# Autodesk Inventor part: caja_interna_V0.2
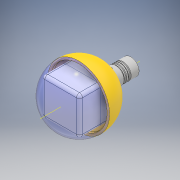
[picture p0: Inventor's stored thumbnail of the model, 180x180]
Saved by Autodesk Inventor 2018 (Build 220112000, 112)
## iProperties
Created: 2018-09
Part Number: caja_interna_V0.2
Material: Generic
Document SubType Name: Modeling
Designer: Gordillo
Density: 1 g/cm^3
Appearance: Default
Author: Gordillo
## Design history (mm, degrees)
sketch "Sketch1"
  geometry: L1 (125, 125)-(-125, 125); L2 (-125, 125)-(-125, -125); L3 (-125, -125)-(125, -125); L4 (125, -125)-(125, 125); L5 (-175, 0)-(175, 0) reference; L6 (0, -175)-(0, 175) reference; 1 further point
  constraints: 8 end point, 2 parallel, 1 horizontal, 1 perpendicular, 2 other
  dimensions: "d0" = 250 distance of L3.end L2.end; "d1" = 250 distance of L2.end L1.end
extrude "Extrusion1" new body sketch "Sketch1" distance "d2" = 220; taper "d3" = 0 deg
fillet "Fillet1" dims "d5" = 20
sketch "Sketch2"
  geometry: L1 (20, 125)-(220, 125) reference; L2 (120, 125)-(120, -125); L3 (220, -125)-(20, -125) reference; L4 (120, 125)-(120, 205); L5 (120, 0)-(-80, 0); L6 (-153.152, 0)-(282.192, 0) reference; A1 r 203.001 centre (122.991, 2.021) between (120, 205) and (-80, 0); 1 further point
  constraints: 6 end point, 3 midpoint, 2 point on circle, 1 centre point, 1 horizontal, 1 vertical
  dimensions: "d6" = 200 distance of L5.start L5.end; "d8" = 80 distance of L2.start L4.end
revolve "Revolution1" sketch "Sketch2" stored, may be unused: angle "d9" = 90 deg
combine "Combine1"
shell "Shell2" dims "d10" = 25
sketch "Sketch3"
  geometry: L1 (100, 100)-(100, -100) reference; L2 (100, -100)-(-100, -100) reference; L3 (-100, -100)-(-100, 100) reference; L4 (-100, 100)-(100, 100) reference; L5 (105, 125)-(-105, 125) reference; L6 (-125, 105)-(-125, -105) reference; L7 (-105, -125)-(105, -125) reference; L8 (125, -105)-(125, 105) reference; L9 (-105, 125)-(105, 125) reference; L10 (125, 105)-(125, -105) reference; L11 (105, -125)-(-105, -125) reference; L12 (-125, -105)-(-125, 105) reference; L13 (-105, 125)-(105, 125) reference; L14 (105, 125)-(-105, 125); L15 (-105, 125)-(-125, 105); L16 (-125, -105)-(-125, 105) reference; L17 (-125, -105)-(-105, -125); L18 (125, 105)-(125, -105) reference; L19 (105, -125)-(125, -105); L20 (125, -105)-(125, 105); L21 (-125, 105)-(-105, 105) reference; L22 (-125, 105)-(-125, -105); L23 (-105, -125)-(105, -125); C1 r 205 at (0, 0) reference; C2 r 189 at (0, 0); C3 r 205 at (0, 0) reference; A1 r 20 centre (105, 105) between (125, 105) and (105, 125) reference; A2 r 20 centre (-105, 105) between (-105, 125) and (-125, 105) reference; A3 r 20 centre (-105, -105) between (-125, -105) and (-105, -125) reference; A4 r 20 centre (105, -105) between (105, -125) and (125, -105) reference; A5 r 20 centre (-105, 105) between (-105, 125) and (-125, 105) reference; A6 r 20 centre (105, 105) between (125, 105) and (105, 125) reference; A7 r 20 centre (105, -105) between (105, -125) and (125, -105) reference; A8 r 20 centre (-105, -105) between (-125, -105) and (-105, -125) reference; A9 r 20 centre (105, 105) between (125, 105) and (105, 125) reference; A10 r 20 centre (105, 105) between (125, 105) and (105, 125); A11 r 20 centre (105, -105) between (105, -125) and (125, -105) reference; A12 r 20 centre (105, -105) between (105, -125) and (125, -105); A13 r 20 centre (-105, -105) between (-125, -105) and (-105, -125); A14 r 20 centre (-105, 105) between (-105, 125) and (-125, 105) reference; A15 r 20 centre (-105, 105) between (-105, 125) and (-125, 105); A16 r 20 centre (-105, -105) between (-125, -105) and (-105, -125); A17 r 20 centre (-105, -105) between (-125, -105) and (-105, -125); A18 r 20 centre (105, -105) between (105, -125) and (125, -105); A19 r 20 centre (-105, -105) between (-125, -105) and (-105, -125) reference; A20 r 20 centre (-105, -105) between (-125, -105) and (-105, -125); 1 further point
  constraints: 16 point on circle, 14 end point, 9 centre point, 3 perpendicular, 3 tangent, 2 collinear, 1 concentric, 1 vertical
  dimensions: "d11" = 16 radial gap between concentric circles of C1 C2
extrude "Extrusion2" join sketch "Sketch3" distance "d12" = 20; taper "d13" = 0 deg
sketch "Sketch4"
  geometry: L1 (189, 140)-(-189, 140) reference; L2 (205, 120)-(-205, 120) reference; L3 (189, 120)-(189, 140) reference; L4 (189, 140)-(-189, 140) reference; L5 (-189, 120)-(189, 120) reference; L6 (-125, 20)-(-125, 220) reference; L7 (-125, 220)-(-105, 220) reference; L8 (-205, 120)-(-189, 120); L9 (-189, 120)-(-189, 140); L10 (205, 120)-(-205, 120) reference; L11 (-189, 140)-(-125, 140); L12 (0, 120)-(0, 320); L13 (-125, 140)-(0, 140); L14 (0, -168.98)-(0, 453.807) reference; L15 (0, 304)-(-55, 304); L16 (-55, 304)-(-55, 315.014); L17 (0, 304)-(0, 298); L18 (0, 304)-(-55, 304); L19 (-55, 304)-(-55, 315.014); L20 (-87, 304.444)-(-67, 304.444); L21 (-67, 304.444)-(-67, 311.765); A1 r 195 centre (-10.071, 125.26) between (0, 320) and (-205, 120); A2 r 177.861 centre (-12.205, 120.558) between (0, 298) and (-189, 140); A3 r 195 centre (-10.071, 125.26) between (-55, 315.014) and (-205, 120); A4 r 177.861 centre (-12.205, 120.558) between (0, 298) and (-189, 140); 2 further points
  constraints: 24 end point, 11 point on circle, 5 point on line, 4 centre point, 4 perpendicular, 3 vertical, 2 collinear, 2 concentric, 2 midpoint, 1 horizontal
  dimensions: "d14" = 200 distance of L12.start L12.end; "d15" = 195 radius of A1; "d16" = 22 distance of L12.end L17.end; "d26" = 55 distance of L15.start L15.end; "d27" = 16 distance from line of L12.end L15; "d28" = 177.86112 radius of A2; "d30" = 12 distance between parallel lines of L16 L21; "d31" = 20 distance of L20.start L20.end
  node "Projected Loop3"
  node "Projected Loop4"
derived "tubo_electrovalvula_V0.1.ipt"
feature "Move Body1"
feature "Move Body3"
revolve "Revolution4" stored, may be unused: angle "d32" = 90 deg
workplane "Work Plane1"
sketch "Sketch5"
  geometry: L1 (67, 21.765)-(-67, 21.765) reference; L2 (0, 21.765)-(0, 14.444); L3 (67, 14.444)-(-67, 14.444) reference; 2 further points
  constraints: 3 midpoint, 2 end point
hole "Hole1" sketch "Sketch5" at (0, 18.105) diameter "d33" = 3; stored, may be unused: countersink angle "d37" = 90 deg, drill point angle "d39" = 118 deg; dims "d34" = 6, "d35" = 4, "d36" = 2, "d38" = 6
sketch "Sketch6"
  geometry: C1 r 1.5 at (0, 18.105); A1 r 1.5 centre (0, 18.105) between (0, 16.605) and (0, 19.605) reference; A2 r 1.5 centre (0, 18.105) between (0, 16.605) and (0, 19.605) reference; 1 further point
  constraints: 1 centre point, 1 coincident, 1 concentric
extrude "Extrusion3" cut sketch "Sketch6" distance "d40" = 20; taper "d41" = 0 deg
pattern_circular "Circular Pattern1" dims angle "d43" = 360 deg
node "cajacorchopan"
node "semicirculo_inferior"
node "Projected Loop1"
node "Projected Loop2"
feature "Solid1::tubo_electrovalvula_V0.1.ipt" dims "d18" = 10
tag "TaggingFeature1"
node "semicirculo_superior"
node "tubo inflado"
other parameters: "d19" = 270 deg, "d23" = 0
